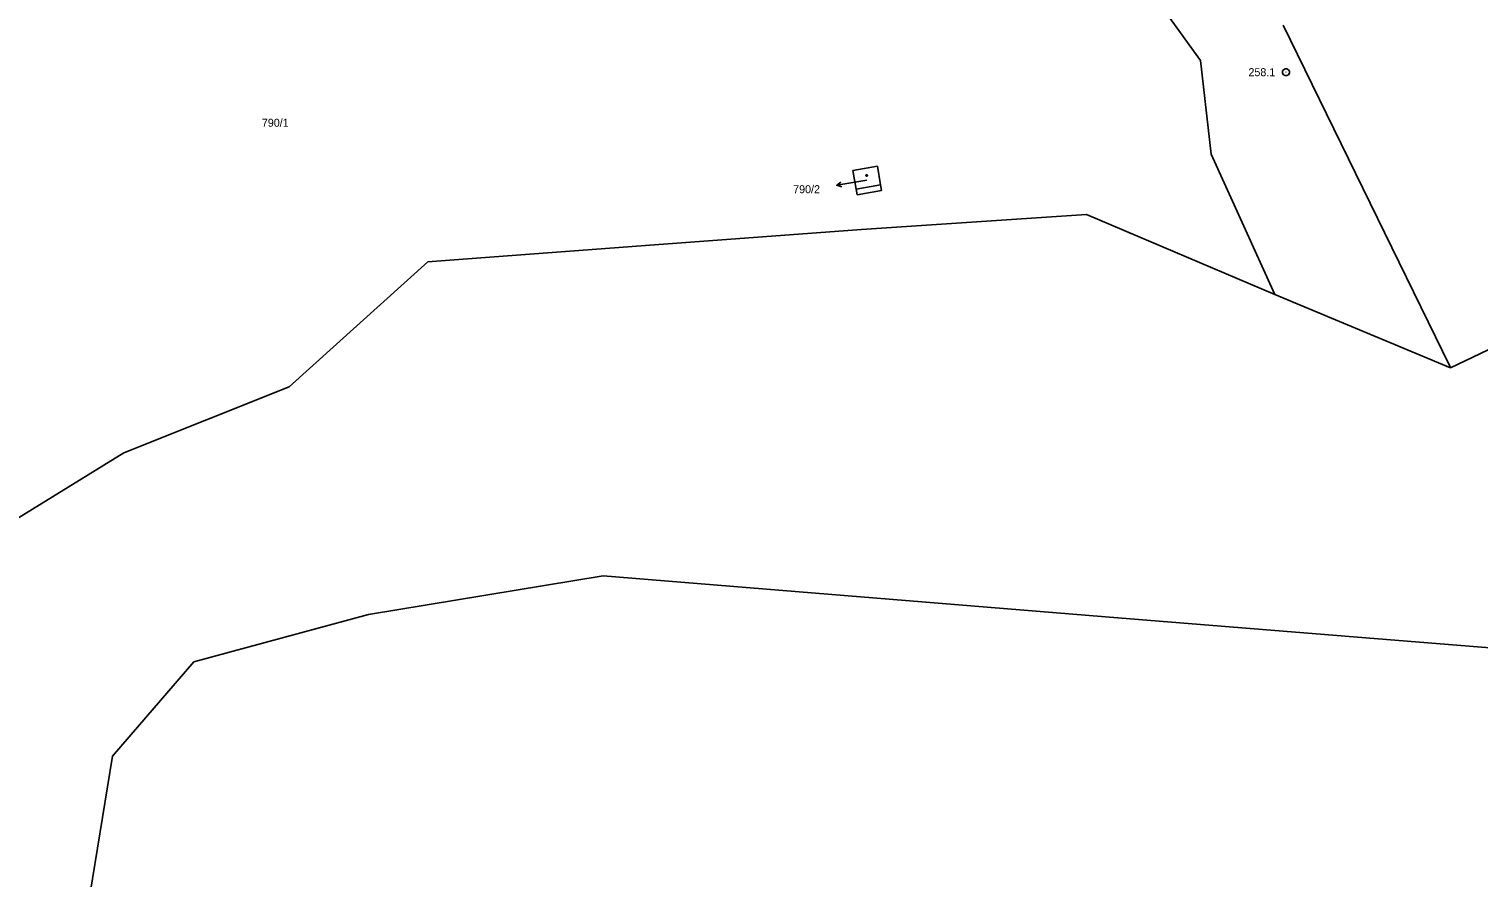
# Model space of a CAD drawing. Extents: x -845995 to -842497, y -1063614 to -1059680.
# Drawn here: x -843659.2 to -843351.4, y -1062182 to -1062001.9 of the extents above; entities that cross this region are included whole.
import ezdxf

# ---------------------------------------------------------------- set-up
doc = ezdxf.new("R2010")
doc.units = 0
for name, color, linetype in [('KN_HRANICE', 7, 'Continuous'), ('KN_KULTURY', 7, 'Continuous'), ('KN_MEZNIKY', 7, 'Continuous'), ('KN_PARCELY', 7, 'Continuous'), ('KN_SLUCKY', 7, 'Continuous'), ('KN_STAVEBNI', 7, 'Continuous')]:
    doc.layers.add(name, color=color, linetype=linetype)

# ---------------------------------------------------------------- blocks, each defined once
blk = doc.blocks.new('101')
blk.add_line((-0.05, 0), (0.05, 0))
blk.add_lwpolyline([(0.19, 0.72), (0.53, 0.53), (0.72, 0.19), (0.72, -0.2), (0.53, -0.54), (0.19, -0.73), (-0.2, -0.73), (-0.54, -0.54), (-0.73, -0.2), (-0.73, 0.19), (-0.54, 0.53), (-0.2, 0.72), (0.19, 0.72)])
blk = doc.blocks.new('10292')
blk.add_line((0, 3), (0, 0))
blk.add_lwpolyline([(-0.5, 2), (0, 3), (0.5, 2)])
blk = doc.blocks.new('402')
blk.add_lwpolyline([(0.09, 0.15), (0.18, 0), (0.09, -0.15), (-0.09, -0.15), (-0.18, 0), (-0.09, 0.15), (0.09, 0.15)])

msp = doc.modelspace()

# ---------------------------------------------------------------- linework, layer by layer
at = {"layer": 'KN_HRANICE'}
for p, q in [((-843447.74, -1061956.71), (-843410.34, -1062008.61)), ((-843357.43, -1062073.51), (-843392.79, -1062001.1)), ((-843410.34, -1062008.61), (-843408.1, -1062028.48)), ((-843484.2, -1062031.99), (-843478.99, -1062031.04)), ((-843478.99, -1062031.04), (-843478.31, -1062034.99)), ((-843408.1, -1062028.48), (-843394.55, -1062058.3)), ((-843483.48, -1062035.92), (-843484.2, -1062031.99)), ((-843483.29, -1062037.13), (-843483.48, -1062035.92)), ((-843478.1, -1062036.2), (-843483.29, -1062037.13)), ((-843478.31, -1062034.99), (-843478.1, -1062036.2)), ((-843434.57, -1062041.33), (-843482.38, -1062044.5)), ((-843394.55, -1062058.3), (-843434.57, -1062041.33)), ((-843482.38, -1062044.5), (-843525.38, -1062047.66)), ((-843525.38, -1062047.66), (-843569.83, -1062051)), ((-843304, -1062048.33), (-843357.26, -1062073.88)), ((-843574.5, -1062051.35), (-843603.92, -1062077.87)), ((-843569.83, -1062051), (-843574.5, -1062051.35)), ((-843357.26, -1062073.88), (-843394.55, -1062058.3)), ((-843357.26, -1062073.88), (-843357.43, -1062073.51)), ((-843603.92, -1062077.87), (-843639.07, -1062091.95)), ((-843639.07, -1062091.95), (-843668.06, -1062109.81)), ((-843587.08, -1062126.23), (-843537.23, -1062118.05)), ((-843537.23, -1062118.05), (-843427.91, -1062126.94)), ((-843624.14, -1062136.31), (-843587.08, -1062126.23)), ((-843427.91, -1062126.94), (-843319.99, -1062135.71)), ((-843641.42, -1062156.35), (-843624.14, -1062136.31)), ((-843651.36, -1062217.31), (-843641.42, -1062156.35))]:
    msp.add_line(p, q, dxfattribs=at)
at = {"layer": 'KN_PARCELY'}
msp.add_line((-843481.26, -1062034.04), (-843484.66, -1062034.6), dxfattribs=at)
at = {"layer": 'KN_SLUCKY'}
msp.add_line((-843483.48, -1062035.92), (-843478.31, -1062034.99), dxfattribs=at)
at = {"layer": 'KN_STAVEBNI'}
for p, q in [((-843484.2, -1062031.99), (-843478.99, -1062031.04)), ((-843478.99, -1062031.04), (-843478.31, -1062034.99)), ((-843483.48, -1062035.92), (-843484.2, -1062031.99)), ((-843483.48, -1062035.92), (-843478.31, -1062034.99))]:
    msp.add_line(p, q, dxfattribs=at)

# ---------------------------------------------------------------- block references
at = {"layer": 'KN_KULTURY'}
msp.add_blockref('402', (-843481.26, -1062033), dxfattribs=at)
at = {"layer": 'KN_MEZNIKY'}
msp.add_blockref('101', (-843392.2, -1062011.08), dxfattribs=at)
at = {"layer": 'KN_PARCELY', "rotation": 99.29358599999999}
msp.add_blockref('10292', (-843484.66, -1062034.6), dxfattribs=at)

# ---------------------------------------------------------------- texts
at = {"layer": 'KN_MEZNIKY'}
msp.add_text('258.1', height=1.7, dxfattribs=at).set_placement((-843400.17, -1062011.93))
at = {"layer": 'KN_PARCELY'}
for s, height, p in [('790/1', 1.7, (-843609.72, -1062022.67)), ('790/2', 0.1, (-843481.5, -1062034.04)), ('790/2', 1.7, (-843496.87, -1062036.78))]:
    msp.add_text(s, height=height, dxfattribs=at).set_placement(p)

doc.saveas('drawing.dxf')
